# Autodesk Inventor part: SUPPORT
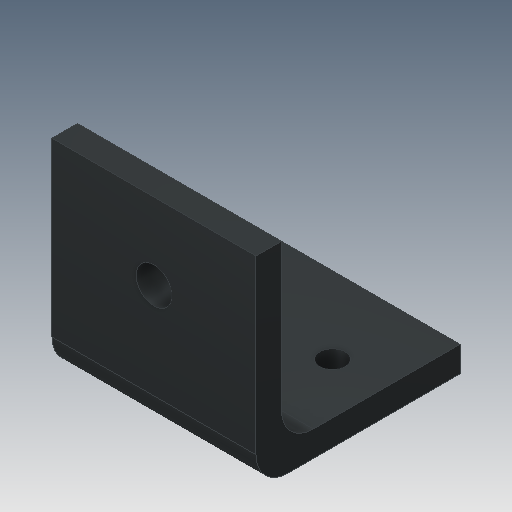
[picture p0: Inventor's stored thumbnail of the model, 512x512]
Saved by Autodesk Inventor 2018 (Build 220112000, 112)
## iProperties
Created: 2016-05
Part Number: SUPPORT
Material: Iron, Cast
Document SubType Name: Modeling
Designer: CADCIM
Density: 7.15 g/cm^3
Appearance: Iron Gray
Mass: 104.47 g
Surface Area: 70.4692 cm^2
Volume: 14.6112 cm^3
Author: CADCIM
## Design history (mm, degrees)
sketch "Sketch1"
  geometry: L1 (0, 0)-(40, 0); L2 (40, 0)-(40, -5); L3 (40, -5)-(5, -5); L4 (5, -5)-(5, -40); L5 (5, -40)-(0, -40); L6 (0, -40)-(0, 0)
  constraints: 12 end point, 2 parallel, 2 perpendicular, 1 horizontal
  dimensions: "d2" = 40 distance between parallel lines of L6 L2; "d3" = 40 distance of L5.end L1.start; "d4" = 5 distance between parallel lines of L1 L3
extrude "Extrusion1" new body sketch "Sketch1" distance "d0" = 40; taper "d1" = 0 deg
sketch "Sketch2"
  geometry: L1 (0, 0)-(0, 35) reference; L2 (0, 35)-(-40, 35) reference; C1 r 3.5 at (-20, 20); 1 further point
  constraints: 1 centre point
  dimensions: "d5" = 7 diameter of C1; "d6" = 20 distance from line of C1.centre L1; "d7" = 15 distance from line of L2 C1.centre
extrude "Extrusion2" cut sketch "Sketch2" distance "d8" = 40; taper "d9" = 0 deg
sketch "Sketch3"
  geometry: L1 (40, 35)-(40, 0) reference; L2 (0, 35)-(40, 35) reference; C1 r 2.5 at (10, 20); C2 r 2.5 at (30, 20); 1 further point
  constraints: 2 centre point, 1 equal radius, 1 horizontal alignment
  dimensions: "d10" = 20 distance of C2.centre C1.centre; "d11" = 10 distance from line of L1 C2.centre; "d12" = 15 distance from line of L2 C2.centre; "d13" = 5 diameter of C1
extrude "Extrusion3" cut sketch "Sketch3" distance "d14" = 40; taper "d15" = 0 deg
fillet "Fillet1" dims "d16" = 6.25
body "Solid1"
